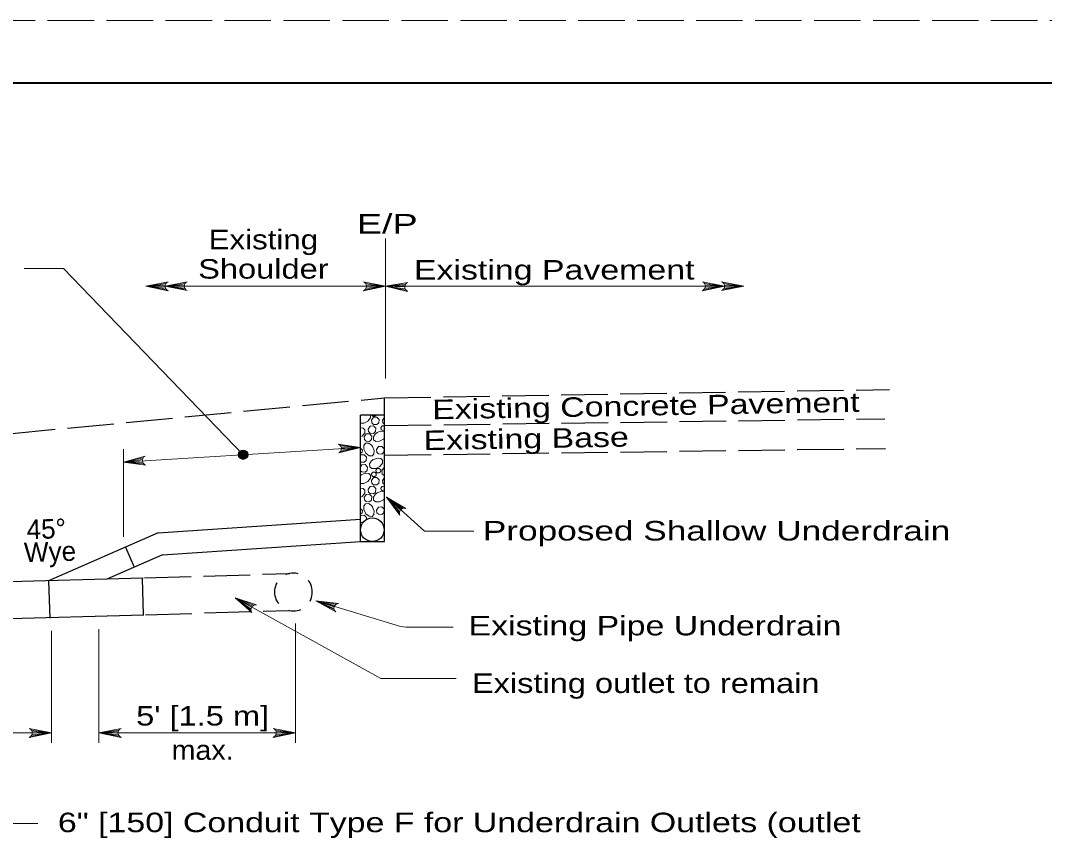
# Model space of a CAD drawing. Extents: x 743.9 to 777.9, y 1051 to 1073.
# Drawn here: x 748.95 to 757.15, y 1066.47 to 1073.02 of the extents above; entities that cross this region are included whole.
import ezdxf
from ezdxf.enums import TextEntityAlignment as Align

# ---------------------------------------------------------------- set-up
doc = ezdxf.new("R2010")
doc.units = 0
doc.header["$LTSCALE"] = 0.062
doc.linetypes.add('DOTTED', pattern=[1.5, 0.3, -1.2])
doc.linetypes.add('LONG_DASHED', pattern=[7.5, 6, -1.5])
doc.layers.add('1', color=7, linetype='Continuous', lineweight=13)

msp = doc.modelspace()

# ---------------------------------------------------------------- hatches: boundary and pattern name
at = {"layer": '1'}
msp.add_hatch(color=256, dxfattribs=at).paths.add_polyline_path([(750.77368, 1069.54413, 1), (750.69911, 1069.54413, 1)])

# ---------------------------------------------------------------- linework, layer by layer
at = {"layer": '1', "lineweight": 25}
for p, q in [((745.86317, 1072.51808), (777.36317, 1072.51808)), ((751.67608, 1069.86175), (751.86733, 1069.86175)), ((751.67608, 1068.849), (751.67608, 1069.86108)), ((751.86733, 1068.84825), (751.86733, 1069.86175)), ((750.05483, 1068.91775), (751.67608, 1069.0285)), ((750.05483, 1068.91775), (749.17767, 1068.53483)), ((749.79567, 1068.8045), (749.86508, 1068.64533)), ((750.09033, 1068.7435), (751.67608, 1068.849)), ((751.67608, 1068.84825), (751.86733, 1068.84825)), ((750.09033, 1068.7435), (749.64417, 1068.54883)), ((747.94125, 1068.50342), (749.93525, 1068.55775)), ((749.19033, 1068.23725), (749.18125, 1068.53275)), ((749.939, 1068.26183), (749.93, 1068.55292)), ((747.95033, 1068.20867), (749.9415, 1068.26283))]:
    msp.add_line(p, q, dxfattribs=at)
at = {"layer": '1'}
for p, q in [((751.87708, 1070.15308), (751.87708, 1071.27258)), ((750.11825, 1070.914), (749.95808, 1070.8915)), ((750.11283, 1070.90292), (749.95808, 1070.8915)), ((750.27142, 1070.91442), (750.11125, 1070.89158)), ((750.266, 1070.90325), (750.11125, 1070.89158)), ((751.71683, 1070.91392), (751.87708, 1070.8915)), ((751.72225, 1070.90283), (751.87708, 1070.8915)), ((752.038, 1070.90883), (751.87708, 1070.8915)), ((754.42992, 1070.91392), (754.59017, 1070.89117)), ((754.43533, 1070.90283), (754.59017, 1070.89117)), ((754.58383, 1070.91433), (754.744, 1070.8915)), ((754.58917, 1070.90325), (754.744, 1070.8915)), ((750.11125, 1070.89158), (749.95808, 1070.8915)), ((750.11408, 1070.87717), (749.95808, 1070.8915)), ((750.12017, 1070.86683), (749.95808, 1070.8915)), ((749.95808, 1070.8915), (754.744, 1070.8915)), ((750.26442, 1070.89192), (750.11125, 1070.89158)), ((750.26725, 1070.87758), (750.11125, 1070.89158)), ((750.27342, 1070.86717), (750.11125, 1070.89158)), ((751.715, 1070.86675), (751.87708, 1070.8915)), ((751.72108, 1070.87708), (751.87708, 1070.8915)), ((751.72392, 1070.8915), (751.87708, 1070.8915)), ((752.03217, 1070.89792), (751.87708, 1070.8915)), ((752.03017, 1070.88667), (751.87708, 1070.8915)), ((752.03258, 1070.87217), (751.87708, 1070.8915)), ((752.03833, 1070.86158), (751.87708, 1070.8915)), ((754.42792, 1070.86675), (754.59017, 1070.89117)), ((754.43408, 1070.87717), (754.59017, 1070.89117)), ((754.437, 1070.8915), (754.59017, 1070.89117)), ((754.58175, 1070.86717), (754.744, 1070.8915)), ((754.58792, 1070.87758), (754.744, 1070.8915)), ((754.59083, 1070.89192), (754.744, 1070.8915)), ((751.85092, 1069.82108), (751.86733, 1069.84433)), ((749.77733, 1069.48417), (751.67608, 1069.60283)), ((751.515, 1069.61692), (751.67617, 1069.60283)), ((751.5155, 1069.56967), (751.67617, 1069.60283)), ((751.521, 1069.60608), (751.67617, 1069.60283)), ((751.52108, 1069.58033), (751.67617, 1069.60283)), ((751.52317, 1069.59492), (751.67617, 1069.60283)), ((751.57417, 1069.59642), (751.67608, 1069.60283)), ((749.77733, 1068.88683), (749.77733, 1069.58783)), ((749.93558, 1069.518), (749.77733, 1069.48417)), ((749.93092, 1069.50658), (749.77733, 1069.48417)), ((749.93008, 1069.49517), (749.77733, 1069.48417)), ((749.93392, 1069.481), (749.77733, 1069.48417)), ((749.94083, 1069.47108), (749.77733, 1069.48417)), ((749.89867, 1069.49175), (749.79667, 1069.48542)), ((751.67608, 1069.37808), (751.68292, 1069.3835)), ((751.85092, 1069.33783), (751.86733, 1069.36108)), ((751.99667, 1069.10275), (751.883, 1069.20542)), ((751.98908, 1069.09017), (751.883, 1069.20542)), ((751.98667, 1069.07833), (751.883, 1069.20542)), ((752.0055, 1069.11), (751.883, 1069.20542)), ((752.01692, 1069.11467), (751.883, 1069.20542)), ((752.18683, 1068.93092), (751.88408, 1069.20558)), ((752.18683, 1068.93092), (752.58275, 1068.93092)), ((750.80425, 1068.323), (750.67167, 1068.39983)), ((750.79942, 1068.30917), (750.67167, 1068.39983)), ((750.79958, 1068.29708), (750.67167, 1068.39983)), ((750.81133, 1068.332), (750.67167, 1068.39983)), ((750.82158, 1068.33883), (750.67167, 1068.39983)), ((751.46517, 1068.328), (751.31908, 1068.374)), ((751.46358, 1068.31342), (751.31908, 1068.374)), ((751.46633, 1068.30167), (751.31908, 1068.374)), ((751.47017, 1068.33833), (751.31908, 1068.374)), ((751.47867, 1068.34725), (751.31908, 1068.374)), ((751.98725, 1068.17292), (751.32183, 1068.37417)), ((749.20083, 1067.23917), (749.20083, 1068.1335)), ((749.58092, 1067.23917), (749.58092, 1068.14883)), ((751.15475, 1067.23917), (751.15475, 1068.19467)), ((752.0555, 1068.16283), (752.4165, 1068.16283)), ((749.03875, 1067.293), (749.20083, 1067.31783)), ((749.04058, 1067.34025), (749.20083, 1067.31783)), ((749.04483, 1067.30342), (749.20083, 1067.31783)), ((749.046, 1067.32917), (749.20083, 1067.31783)), ((749.04767, 1067.31783), (749.20083, 1067.31783)), ((749.74217, 1067.34025), (749.58192, 1067.31783)), ((749.73675, 1067.32917), (749.58192, 1067.31783)), ((749.73508, 1067.31783), (749.58192, 1067.31783)), ((749.73792, 1067.30342), (749.58192, 1067.31783)), ((749.74408, 1067.293), (749.58192, 1067.31783)), ((749.58192, 1067.31783), (751.15475, 1067.31783)), ((750.99267, 1067.293), (751.15475, 1067.31783)), ((750.9945, 1067.34025), (751.15475, 1067.31783)), ((750.99875, 1067.30342), (751.15475, 1067.31783)), ((751, 1067.32917), (751.15475, 1067.31783)), ((751.00158, 1067.31783), (751.15475, 1067.31783))]:
    msp.add_line(p, q, dxfattribs=at)
at = {"layer": '1', "linetype": 'LONG_DASHED', "lineweight": 25}
for p, q in [((747.92125, 1069.62217), (751.86733, 1069.99925)), ((751.86733, 1069.99925), (755.90942, 1070.06592)), ((751.86733, 1069.86175), (751.86733, 1069.99925)), ((751.87017, 1069.77717), (755.87433, 1069.8315)), ((751.86892, 1069.53975), (755.87758, 1069.59408)), ((749.94783, 1068.55825), (751.1095, 1068.59383)), ((749.95383, 1068.26325), (751.10167, 1068.29858))]:
    msp.add_line(p, q, dxfattribs=at)
at = {"layer": '1', "linetype": 'LONG_DASHED'}
msp.add_lwpolyline([(743.86317, 1051.01808), (777.86317, 1051.01808), (777.86317, 1073.01808), (743.86317, 1073.01808)], close=True, dxfattribs=at)
at = {"layer": '1', "lineweight": 40}
msp.add_lwpolyline([(745.86317, 1072.51808), (777.36317, 1072.51808), (777.36317, 1051.51808), (745.86317, 1051.51808)], close=True, dxfattribs=at)
msp.add_lwpolyline([(745.86317, 1072.51808), (777.36317, 1072.51808), (777.36317, 1051.51808), (745.86317, 1051.51808)], close=True, dxfattribs=at)
at = {"layer": '1'}
for points in [[(750.73642, 1069.54417), (749.29942, 1071.03467), (748.98233, 1071.03467)], [(750.13508, 1070.85617), (749.95808, 1070.8915), (750.135, 1070.927)], [(750.28833, 1070.85658), (750.11125, 1070.89158), (750.28817, 1070.92742)], [(751.70008, 1070.85608), (751.87708, 1070.8915), (751.70008, 1070.92692)], [(752.05292, 1070.8505), (751.87708, 1070.8915), (752.05517, 1070.92125)], [(754.41308, 1070.85617), (754.59017, 1070.89117), (754.41325, 1070.927)], [(754.56692, 1070.85658), (754.744, 1070.8915), (754.56708, 1070.92742)], [(751.75617, 1069.86108), (751.75583, 1069.83942), (751.73475, 1069.81258), (751.70242, 1069.79633), (751.67608, 1069.79592)], [(751.80083, 1069.86108), (751.80075, 1069.86025), (751.79083, 1069.85183), (751.77467, 1069.85308), (751.76717, 1069.86033), (751.76708, 1069.86108)], [(751.86733, 1069.86025), (751.86533, 1069.86025), (751.864, 1069.86108)], [(751.67608, 1069.75817), (751.69633, 1069.75633), (751.71008, 1069.74333), (751.70975, 1069.71967), (751.68883, 1069.69292), (751.67608, 1069.68658)], [(751.8385, 1069.75942), (751.84858, 1069.77392), (751.865, 1069.77483), (751.86733, 1069.77225)], [(751.86733, 1069.74083), (751.8645, 1069.7385), (751.8485, 1069.7395), (751.84108, 1069.74683), (751.83858, 1069.75942)], [(751.86733, 1069.78808), (751.855, 1069.80008), (751.85092, 1069.82108)], [(751.86733, 1069.67592), (751.86067, 1069.66733), (751.82825, 1069.65117), (751.79783, 1069.6505), (751.78058, 1069.66292), (751.779, 1069.68717), (751.79292, 1069.70892), (751.80892, 1069.72175)], [(751.80767, 1069.72075), (751.83925, 1069.73333), (751.86733, 1069.73083)], [(751.50125, 1069.55833), (751.67617, 1069.60283), (751.49758, 1069.629)], [(751.67608, 1069.59125), (751.67992, 1069.5915), (751.69117, 1069.57975), (751.68975, 1069.56333), (751.67967, 1069.55508), (751.67608, 1069.55525)], [(751.77317, 1069.60842), (751.78575, 1069.57683), (751.78317, 1069.54767), (751.77, 1069.53383), (751.7465, 1069.53433), (751.71958, 1069.55525), (751.70342, 1069.58767), (751.703, 1069.61817), (751.71508, 1069.6355), (751.73942, 1069.63708), (751.76125, 1069.62317), (751.77392, 1069.60717)], [(751.8035, 1069.5845), (751.82042, 1069.6085), (751.8475, 1069.61008), (751.86625, 1069.59067), (751.8635, 1069.56333), (751.847, 1069.5495), (751.82025, 1069.55133), (751.80767, 1069.56358), (751.80358, 1069.5845)], [(749.95642, 1069.4615), (749.77733, 1069.48417), (749.95133, 1069.53217)], [(751.67608, 1069.5375), (751.67933, 1069.54208), (751.70625, 1069.5435), (751.725, 1069.52408), (751.72233, 1069.49683), (751.70558, 1069.48292), (751.67883, 1069.48483), (751.67608, 1069.4875)], [(751.77683, 1069.50392), (751.80858, 1069.51633), (751.83767, 1069.51383), (751.85142, 1069.50067), (751.85108, 1069.47717), (751.83, 1069.45033), (751.79767, 1069.43408), (751.76708, 1069.43367), (751.74992, 1069.44583), (751.74833, 1069.47017), (751.76225, 1069.49192), (751.77825, 1069.50467)], [(751.67608, 1069.44783), (751.68667, 1069.46283), (751.71383, 1069.46433), (751.7325, 1069.445), (751.72983, 1069.4175), (751.71317, 1069.40375), (751.68642, 1069.40567), (751.67608, 1069.41567)], [(751.86733, 1069.377), (751.86533, 1069.377), (751.84808, 1069.38917), (751.84642, 1069.41358), (751.86042, 1069.43533), (751.86733, 1069.44092)], [(751.68167, 1069.38275), (751.71333, 1069.39533), (751.74242, 1069.39283), (751.75617, 1069.37967), (751.75583, 1069.356), (751.73475, 1069.32933), (751.70242, 1069.313), (751.67608, 1069.3125)], [(751.67608, 1069.27508), (751.69633, 1069.27325), (751.71008, 1069.26008), (751.70975, 1069.2365), (751.68883, 1069.20967), (751.67608, 1069.20333)], [(751.8385, 1069.27617), (751.84858, 1069.29058), (751.865, 1069.2915), (751.86733, 1069.289)], [(751.86733, 1069.2575), (751.8645, 1069.25525), (751.8485, 1069.25633), (751.84108, 1069.26358), (751.83858, 1069.27617)], [(751.86733, 1069.30467), (751.855, 1069.31683), (751.85092, 1069.33783)], [(751.86733, 1069.19258), (751.86067, 1069.18392), (751.82825, 1069.16792), (751.79783, 1069.16742), (751.78058, 1069.17958), (751.779, 1069.20375), (751.79292, 1069.22567), (751.80892, 1069.23833)], [(751.80767, 1069.23767), (751.83925, 1069.25008), (751.86733, 1069.24758)], [(751.99058, 1069.0605), (751.883, 1069.20542), (752.03808, 1069.113)], [(751.67608, 1069.108), (751.67992, 1069.10817), (751.69117, 1069.09667), (751.68975, 1069.08017), (751.67967, 1069.07175), (751.67608, 1069.072)], [(751.77317, 1069.12517), (751.78575, 1069.0935), (751.78317, 1069.0645), (751.77, 1069.05058), (751.7465, 1069.051), (751.71958, 1069.072), (751.70342, 1069.10442), (751.703, 1069.135), (751.71508, 1069.15208), (751.73942, 1069.15383), (751.76125, 1069.13992), (751.77392, 1069.12375)], [(751.8035, 1069.10108), (751.82042, 1069.12525), (751.8475, 1069.12675), (751.86625, 1069.10742), (751.8635, 1069.08008), (751.847, 1069.06608), (751.82025, 1069.06817), (751.80767, 1069.08017), (751.80358, 1069.10108)], [(751.67608, 1069.05425), (751.67933, 1069.05883), (751.70625, 1069.06025), (751.725, 1069.04075), (751.7235, 1069.02533)], [(751.6945, 1069.00042), (751.67883, 1069.00158), (751.67608, 1069.00442)], [(750.80708, 1068.28042), (750.67167, 1068.39983), (750.84258, 1068.34167)], [(750.67167, 1068.39983), (751.83733, 1067.75208), (752.44175, 1067.75208)], [(751.47725, 1068.28708), (751.31908, 1068.374), (751.49858, 1068.35458)], [(747.84467, 1067.31783), (748.63167, 1067.31783), (749.20083, 1067.31783)], [(748.6155, 1067.31817), (748.75717, 1066.59367), (749.0915, 1066.59367)], [(749.02383, 1067.28242), (749.20083, 1067.31783), (749.02383, 1067.35325)], [(749.75892, 1067.28242), (749.58192, 1067.31783), (749.75892, 1067.35325)], [(750.97775, 1067.28242), (751.15475, 1067.31783), (750.97775, 1067.35325)]]:
    msp.add_lwpolyline(points, dxfattribs=at)
for points in [[(751.76367, 1069.82008), (751.78058, 1069.84408), (751.80767, 1069.84558), (751.82633, 1069.82608), (751.82375, 1069.79883), (751.807, 1069.78508), (751.78025, 1069.78692), (751.76767, 1069.79908)], [(751.736, 1069.74958), (751.75283, 1069.77358), (751.77983, 1069.77517), (751.79858, 1069.75567), (751.796, 1069.72842), (751.77925, 1069.7145), (751.7525, 1069.71633), (751.73992, 1069.72867)], [(751.704, 1069.68575), (751.72083, 1069.70992), (751.74792, 1069.7115), (751.76675, 1069.69192), (751.76408, 1069.66467), (751.74733, 1069.65075), (751.72067, 1069.65275), (751.70817, 1069.66483)], [(751.79967, 1069.41892), (751.80983, 1069.4335), (751.826, 1069.43425), (751.83725, 1069.42275), (751.83567, 1069.40633), (751.82567, 1069.39792), (751.80967, 1069.39908), (751.80217, 1069.40642)], [(751.76367, 1069.33683), (751.78058, 1069.36083), (751.80767, 1069.36225), (751.82633, 1069.34283), (751.82375, 1069.31558), (751.807, 1069.30167), (751.78025, 1069.30367), (751.76767, 1069.31583)], [(751.76483, 1069.38967), (751.77492, 1069.40408), (751.79108, 1069.405), (751.80242, 1069.39342), (751.80075, 1069.377), (751.79083, 1069.36858), (751.77467, 1069.36975), (751.76717, 1069.377)], [(751.736, 1069.26625), (751.75283, 1069.29033), (751.77983, 1069.29192), (751.79858, 1069.27233), (751.796, 1069.245), (751.77925, 1069.23125), (751.7525, 1069.23308), (751.73992, 1069.24525)], [(751.704, 1069.2025), (751.72083, 1069.22667), (751.74792, 1069.22817), (751.76675, 1069.20875), (751.76408, 1069.18142), (751.74733, 1069.16742), (751.72067, 1069.1695), (751.70817, 1069.18158)]]:
    msp.add_lwpolyline(points, close=True, dxfattribs=at)
at = {"layer": '1', "lineweight": 25}
for centre, radius in [((750.73639, 1069.54413), 0.03728), ((751.77049, 1068.94338), 0.0944)]:
    msp.add_circle(centre, radius, dxfattribs=at)
at = {"layer": '1'}
for radius in [0.01967, 0.000342]:
    msp.add_circle((750.73639, 1069.54413), radius, dxfattribs=at)
for centre, radius, start, end in [((750.14934, 1070.89165), 0.0382, 112.11753, 247.94366), ((750.30251, 1070.89206), 0.0382, 112.21677, 248.0429), ((751.6858, 1070.89155), 0.0382, 292.08605, 67.91218), ((752.06829, 1070.88546), 0.0382, 110.26286, 246.08899), ((754.39884, 1070.89165), 0.0382, 291.93968, 67.76581), ((754.55269, 1070.89208), 0.0382, 291.92813, 67.75426), ((751.48511, 1069.59296), 0.0382, 295.04757, 70.8737), ((749.96813, 1069.49789), 0.0382, 116.18013, 252.00626), ((752.02498, 1069.07721), 0.0382, 69.99143, 205.81756), ((750.83722, 1068.30393), 0.0382, 81.99232, 217.81845), ((751.50157, 1068.3166), 0.0382, 94.60393, 230.43006), ((752.05546, 1068.39887), 0.23599, 253.17419, 270), ((749.00956, 1067.31785), 0.0382, 292.08605, 67.91218), ((749.77321, 1067.31785), 0.0382, 112.08782, 247.91395), ((750.96349, 1067.31785), 0.0382, 292.08605, 67.91218)]:
    msp.add_arc(centre, radius, start, end, dxfattribs=at)
at = {"layer": '1', "linetype": 'DOTTED', "lineweight": 25}
for start, end in [(0, 180), (180, 0)]:
    msp.add_arc((751.1387, 1068.4454), 0.15139, start, end, dxfattribs=at)

# ---------------------------------------------------------------- texts
at = {"layer": '1'}
for s, width, p in [('E/P', 1.45, (751.64592, 1071.31367)), ('Proposed Shallow Underdrain', 1.35, (752.65567, 1068.8575)), ('Existing Pipe Underdrain', 1.3, (752.54075, 1068.09833)), ('Existing outlet to remain', 1.25, (752.56742, 1067.63758)), ('6" [150] Conduit Type F for Underdrain Outlets (outlet', 1.3, (749.25317, 1066.52383))]:
    msp.add_text(s, height=0.156, dxfattribs=dict(at, width=width)).set_placement(p)
for s, width, p in [('Existing', 1.2, (750.89821, 1071.18742)), ('Shoulder', 1.25, (750.89825, 1070.95275)), ("5' [1.5 m]", 1.25, (750.412, 1067.37683)), ('max.', 1.1, (750.412, 1067.10283))]:
    msp.add_text(s, height=0.156, dxfattribs=dict(at, width=width)).set_placement(p, align=Align.CENTER)
at = {"layer": '1', "width": 1.3}
for s, rotation, p in [('Existing Pavement', 0.031, (752.10342, 1070.94475)), ('Existing Concrete Pavement', 1, (752.25117, 1069.82742)), ('Existing Base', 1.001, (752.182, 1069.58033))]:
    msp.add_text(s, height=0.156, rotation=rotation, dxfattribs=at).set_placement(p)
at = {"layer": '1'}
for s, p in [('45°', (749.005, 1068.86733)), ('Wye', (748.98433, 1068.68342))]:
    msp.add_text(s, height=0.156, rotation=1.764, dxfattribs=at).set_placement(p)

doc.saveas('drawing.dxf')
